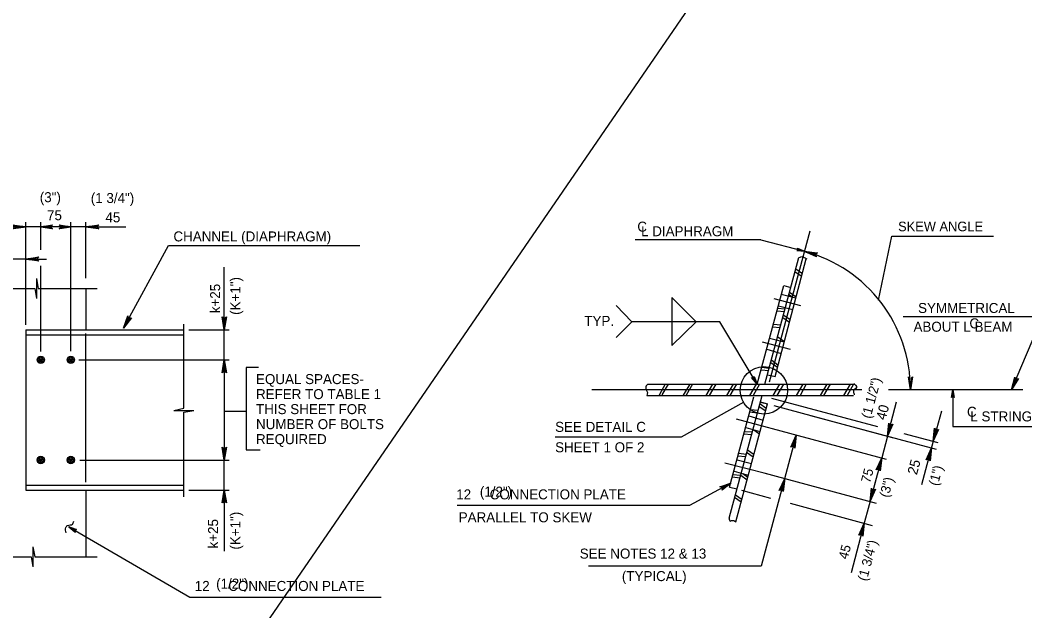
# Model space of a CAD drawing. Extents: x 634656 to 641360, y 298715 to 301183.
# Drawn here: x 640308.6 to 640609.6, y 299068.9 to 299246 of the extents above; entities that cross this region are included whole.
import ezdxf

# ---------------------------------------------------------------- set-up
doc = ezdxf.new("R2010")
doc.units = 0
for name, color, linetype in [('1', 7, 'Continuous'), ('2', 7, 'Continuous'), ('40', 7, 'Continuous')]:
    doc.layers.add(name, color=color, linetype=linetype)

msp = doc.modelspace()

# ---------------------------------------------------------------- linework, layer by layer
at = {"layer": '1'}
msp.add_line((641102.54, 300114.62), (640153.96, 298732.63), dxfattribs=at)
for points in [[(640306.55, 299184.47), (640306.69, 299184.2), (640310.24, 299184.01), (640306.55, 299184.47), (640306.36, 299184.63), (640310.24, 299184.01), (640306.69, 299183.83), (640306.56, 299183.57), (640310.24, 299184.01), (640306.36, 299183.39), (640306.56, 299183.57)], [(640318.06, 299183.54), (640317.94, 299183.81), (640314.74, 299184.01), (640318.06, 299183.54), (640318.23, 299183.38), (640314.74, 299184.01), (640317.94, 299184.18), (640318.05, 299184.45), (640314.74, 299184.01), (640318.23, 299184.62), (640318.05, 299184.45)], [(640320.42, 299184.47), (640320.55, 299184.2), (640323.74, 299184.01), (640320.42, 299184.47), (640320.25, 299184.63), (640323.74, 299184.01), (640320.55, 299183.83), (640320.43, 299183.57), (640323.74, 299184.01), (640320.25, 299183.39), (640320.43, 299183.57)], [(640331.93, 299183.54), (640331.8, 299183.81), (640328.24, 299184.01), (640331.93, 299183.54), (640332.12, 299183.38), (640328.24, 299184.01), (640331.79, 299184.18), (640331.92, 299184.45), (640328.24, 299184.01), (640332.12, 299184.62), (640331.92, 299184.45)], [(640313.93, 299173.92), (640313.8, 299174.19), (640310.24, 299174.38), (640313.93, 299173.92), (640314.12, 299173.76), (640310.24, 299174.38), (640313.79, 299174.56), (640313.92, 299174.82), (640310.24, 299174.38), (640314.12, 299175), (640313.92, 299174.82)], [(640547.03, 299175.27), (640546.97, 299175.56), (640543.59, 299176.67), (640547.03, 299175.27), (640547.17, 299175.06), (640543.59, 299176.67), (640547.06, 299175.92), (640547.25, 299176.14), (640543.59, 299176.67), (640547.49, 299176.26), (640547.25, 299176.14)], [(640341.66, 299156.65), (640341.36, 299156.66), (640339.49, 299153.63), (640341.66, 299156.65), (640341.9, 299156.74), (640339.49, 299153.63), (640341.04, 299156.83), (640340.87, 299157.08), (640339.49, 299153.63), (640340.81, 299157.34), (640340.87, 299157.08)], [(640370.21, 299156.82), (640369.94, 299156.69), (640369.74, 299153.13), (640370.21, 299156.82), (640370.37, 299157.01), (640369.74, 299153.13), (640369.57, 299156.68), (640369.3, 299156.81), (640369.74, 299153.13), (640369.13, 299157.01), (640369.3, 299156.81)], [(640369.28, 299140.44), (640369.55, 299140.58), (640369.74, 299144.13), (640369.28, 299140.44), (640369.12, 299140.25), (640369.74, 299144.13), (640369.92, 299140.58), (640370.18, 299140.45), (640369.74, 299144.13), (640370.36, 299140.25), (640370.18, 299140.45)], [(640575.77, 299138.84), (640575.5, 299138.7), (640575.29, 299135.15), (640575.77, 299138.84), (640575.94, 299139.03), (640575.29, 299135.15), (640575.13, 299138.7), (640574.87, 299138.83), (640575.29, 299135.15), (640574.69, 299139.03), (640574.87, 299138.83)], [(640607.48, 299138.42), (640607.18, 299138.4), (640605.61, 299135.2), (640607.48, 299138.42), (640607.7, 299138.53), (640605.61, 299135.2), (640606.83, 299138.54), (640606.64, 299138.76), (640605.61, 299135.2), (640606.56, 299139.01), (640606.64, 299138.76)], [(640569.85, 299124.73), (640569.55, 299124.67), (640568.45, 299121.28), (640569.85, 299124.73), (640570.05, 299124.87), (640568.45, 299121.28), (640569.19, 299124.76), (640568.97, 299124.95), (640568.45, 299121.28), (640568.85, 299125.19), (640568.97, 299124.95)], [(640539.72, 299118.16), (640540.01, 299118.23), (640541.12, 299121.61), (640539.72, 299118.16), (640539.52, 299118.02), (640541.12, 299121.61), (640540.37, 299118.13), (640540.6, 299117.94), (640541.12, 299121.61), (640540.71, 299117.7), (640540.6, 299117.94)], [(640583.56, 299123.17), (640583.27, 299123.11), (640582.15, 299119.73), (640583.56, 299123.17), (640583.77, 299123.31), (640582.15, 299119.73), (640582.91, 299123.2), (640582.69, 299123.39), (640582.15, 299119.73), (640582.57, 299123.63), (640582.69, 299123.39)], [(640370.21, 299117.82), (640369.94, 299117.69), (640369.74, 299114.13), (640370.21, 299117.82), (640370.37, 299118.01), (640369.74, 299114.13), (640369.57, 299117.68), (640369.3, 299117.81), (640369.74, 299114.13), (640369.13, 299118.01), (640369.3, 299117.81)], [(640580.2, 299114.3), (640580.49, 299114.36), (640581.61, 299117.74), (640580.2, 299114.3), (640579.99, 299114.16), (640581.61, 299117.74), (640580.85, 299114.27), (640581.07, 299114.08), (640581.61, 299117.74), (640581.19, 299113.84), (640581.07, 299114.08)], [(640565.3, 299111.34), (640565.59, 299111.4), (640566.71, 299114.78), (640565.3, 299111.34), (640565.09, 299111.2), (640566.71, 299114.78), (640565.95, 299111.31), (640566.18, 299111.12), (640566.71, 299114.78), (640566.29, 299110.88), (640566.18, 299111.12)], [(640536.24, 299105.14), (640536.53, 299105.21), (640537.64, 299108.59), (640536.24, 299105.14), (640536.03, 299105), (640537.64, 299108.59), (640536.89, 299105.11), (640537.11, 299104.92), (640537.64, 299108.59), (640537.23, 299104.68), (640537.11, 299104.92)], [(640564.63, 299105.23), (640564.33, 299105.17), (640563.21, 299101.79), (640564.63, 299105.23), (640564.83, 299105.37), (640563.21, 299101.79), (640563.97, 299105.26), (640563.75, 299105.46), (640563.21, 299101.79), (640563.63, 299105.7), (640563.75, 299105.46)], [(640369.28, 299101.44), (640369.55, 299101.58), (640369.74, 299105.13), (640369.28, 299101.44), (640369.12, 299101.25), (640369.74, 299105.13), (640369.92, 299101.58), (640370.18, 299101.45), (640369.74, 299105.13), (640370.36, 299101.25), (640370.18, 299101.45)], [(640560.06, 299091.72), (640560.35, 299091.78), (640561.46, 299095.17), (640560.06, 299091.72), (640559.86, 299091.58), (640561.46, 299095.17), (640560.71, 299091.69), (640560.94, 299091.5), (640561.46, 299095.17), (640561.06, 299091.26), (640560.94, 299091.5)]]:
    msp.add_lwpolyline(points, dxfattribs=at)
at = {"layer": '2'}
for p, q in [((640310.24, 299184.01), (640297.12, 299184.01)), ((640310.24, 299154.63), (640310.24, 299185.38)), ((640328.24, 299184.01), (640310.24, 299184.01)), ((640314.74, 299177.13), (640314.74, 299185.38)), ((640323.74, 299184.01), (640315.12, 299184.01)), ((640323.74, 299146.76), (640323.74, 299185.38)), ((640328.24, 299168.62), (640328.24, 299185.38)), ((640328.24, 299184.01), (640340.24, 299184.01)), ((640533.11, 299137.58), (640545.24, 299182.83)), ((640565.74, 299162.08), (640569.74, 299181.2)), ((640569.74, 299181.2), (640600.24, 299181.2)), ((640339.49, 299153.63), (640352.97, 299178.4)), ((640352.97, 299178.4), (640410.38, 299178.4)), ((640530.49, 299180.08), (640492.86, 299180.08)), ((640530.49, 299180.08), (640543.61, 299176.7)), ((640310.24, 299154.63), (640310.24, 299175.76)), ((640310.24, 299174.38), (640278.87, 299174.38)), ((640310.24, 299174.38), (640316.49, 299174.38)), ((640314.74, 299146.63), (640314.74, 299172.38)), ((640369.74, 299153.13), (640369.74, 299171.89)), ((640531.74, 299136.83), (640541.86, 299174.83)), ((640534.74, 299139.2), (640544.11, 299174.45)), ((640540.74, 299170.58), (640542.74, 299169.2)), ((640540.99, 299171.45), (640542.99, 299170.08)), ((640313.49, 299168.51), (640313.49, 299162.51)), ((640313.49, 299168.51), (640313.99, 299165.51)), ((640529.36, 299136.83), (640537.36, 299166.45)), ((640537.36, 299166.45), (640539.49, 299165.83)), ((640294.99, 299165.51), (640311.49, 299165.51)), ((640311.24, 299165.51), (640311.24, 299165.51)), ((640311.24, 299165.51), (640312.99, 299165.51)), ((640312.99, 299165.51), (640313.49, 299162.51)), ((640313.49, 299165.51), (640313.49, 299165.51)), ((640313.99, 299165.51), (640315.87, 299165.51)), ((640315.87, 299165.51), (640331.62, 299165.51)), ((640328.24, 299165.38), (640328.24, 299153.13)), ((640503.86, 299162.83), (640503.86, 299155.58)), ((640503.86, 299162.83), (640511.11, 299155.58)), ((640536.61, 299163.83), (640540.99, 299162.7)), ((640538.99, 299163.7), (640540.11, 299162.83)), ((640539.11, 299164.45), (640541.11, 299163.08)), ((640534.36, 299162.58), (640542.36, 299160.45)), ((640535.74, 299160.33), (640540.11, 299159.2)), ((640537.61, 299158.58), (640535.24, 299158.7)), ((640537.74, 299159.33), (640535.49, 299159.58)), ((640537.11, 299156.83), (640539.11, 299155.45)), ((640537.36, 299157.58), (640539.24, 299156.2)), ((640614.86, 299157.08), (640573.11, 299157.08)), ((640605.61, 299135.2), (640614.86, 299157.08)), ((640357.62, 299131.38), (640357.62, 299154.88)), ((640518.24, 299155.58), (640491.86, 299155.58)), ((640503.86, 299155.58), (640503.86, 299148.45)), ((640503.86, 299148.45), (640511.11, 299155.58)), ((640529.36, 299136.83), (640518.24, 299155.58)), ((640536.24, 299153.7), (640533.99, 299153.95)), ((640536.49, 299154.58), (640534.24, 299154.7)), ((640310.24, 299153.13), (640357.62, 299153.13)), ((640310.24, 299153.13), (640310.24, 299105.13)), ((640310.24, 299151.63), (640357.62, 299151.63)), ((640328.24, 299107.51), (640328.24, 299152.01)), ((640359.12, 299153.13), (640371.24, 299153.13)), ((640369.74, 299144.13), (640369.74, 299153.13)), ((640535.61, 299151.08), (640537.61, 299149.7)), ((640530.86, 299149.58), (640539.24, 299147.33)), ((640533.11, 299150.7), (640537.49, 299149.58)), ((640532.24, 299147.33), (640536.61, 299146.08)), ((640314.74, 299144.13), (640314.74, 299144.13)), ((640323.74, 299144.13), (640323.74, 299144.13)), ((640326.12, 299144.13), (640371.24, 299144.13)), ((640369.74, 299144.13), (640369.74, 299114.13)), ((640376.24, 299141.88), (640376.24, 299117.13)), ((640379.99, 299141.88), (640376.24, 299141.88)), ((640532.99, 299141.58), (640530.74, 299141.83)), ((640533.49, 299143.33), (640535.49, 299141.95)), ((640533.74, 299144.08), (640535.61, 299142.7)), ((640532.86, 299140.83), (640530.61, 299141.08)), ((640532.61, 299139.7), (640534.74, 299139.2)), ((640496.61, 299136.83), (640558.61, 299136.83)), ((640501.86, 299136.83), (640499.99, 299133.58)), ((640502.74, 299136.83), (640500.86, 299133.7)), ((640509.24, 299136.83), (640507.24, 299133.58)), ((640509.99, 299136.83), (640508.11, 299133.58)), ((640515.99, 299136.83), (640513.99, 299133.45)), ((640516.99, 299136.83), (640514.99, 299133.45)), ((640522.24, 299136.83), (640520.24, 299133.45)), ((640523.24, 299136.83), (640521.24, 299133.45)), ((640529.11, 299136.83), (640527.11, 299133.45)), ((640530.11, 299136.83), (640528.24, 299133.45)), ((640536.11, 299136.83), (640534.11, 299133.45)), ((640537.24, 299136.83), (640535.24, 299133.45)), ((640543.11, 299136.83), (640541.11, 299133.45)), ((640544.11, 299136.83), (640542.24, 299133.45)), ((640550.24, 299136.83), (640548.24, 299133.45)), ((640551.24, 299136.83), (640549.24, 299133.45)), ((640557.24, 299136.83), (640555.24, 299133.45)), ((640558.24, 299136.83), (640556.36, 299133.45)), ((640560.72, 299135.2), (640479.86, 299135.2)), ((640496.36, 299133.45), (640558.24, 299133.45)), ((640511.86, 299135.2), (640511.86, 299135.2)), ((640520.99, 299096.7), (640530.86, 299133.45)), ((640521.11, 299105.95), (640528.36, 299133.08)), ((640533.67, 299132.7), (640565.46, 299124.18)), ((640608.99, 299135.2), (640568.73, 299135.2)), ((640588.01, 299135.2), (640588.01, 299124.2)), ((640357.62, 299129.63), (640357.62, 299131.38)), ((640525.36, 299131.45), (640506.61, 299120.95)), ((640522.99, 299095.58), (640532.49, 299130.95)), ((640529.99, 299130.2), (640531.99, 299128.83)), ((640530.24, 299131.08), (640532.11, 299129.7)), ((640530.36, 299131.58), (640532.49, 299130.95)), ((640530.36, 299131.45), (640532.49, 299130.95)), ((640534.38, 299130.45), (640569.83, 299120.92)), ((640568.45, 299121.28), (640571.17, 299131.55)), ((640354.62, 299129.01), (640357.62, 299129.63)), ((640354.62, 299129.01), (640360.62, 299129.01)), ((640357.62, 299128.51), (640360.62, 299129.01)), ((640357.62, 299129.01), (640357.62, 299129.01)), ((640357.62, 299126.76), (640357.62, 299128.51)), ((640357.62, 299127.76), (640357.62, 299127.76)), ((640357.62, 299103.13), (640357.62, 299127.01)), ((640369.74, 299128.76), (640376.37, 299128.76)), ((640526.86, 299127.33), (640531.24, 299126.08)), ((640529.49, 299128.2), (640527.11, 299128.45)), ((640529.61, 299128.95), (640527.36, 299129.2)), ((640545.36, 299127.5), (640582.99, 299117.37)), ((640584.61, 299128.81), (640582.15, 299119.73)), ((640523.11, 299126.45), (640536.47, 299122.84)), ((640525.99, 299123.83), (640530.24, 299122.7)), ((640588.01, 299124.2), (640624.76, 299124.2)), ((640506.61, 299120.95), (640468.86, 299120.95)), ((640527.74, 299121.7), (640525.36, 299121.83)), ((640527.86, 299122.45), (640525.61, 299122.58)), ((640528.11, 299123.33), (640530.11, 299121.95)), ((640541.12, 299121.61), (640530.61, 299082.33)), ((640536.47, 299122.85), (640568.08, 299114.42)), ((640568.45, 299121.28), (640566.71, 299114.79)), ((640573.33, 299122.08), (640583.49, 299119.37)), ((640582.15, 299119.73), (640578.61, 299106.67)), ((640376.24, 299117.13), (640380.49, 299117.13)), ((640525.86, 299115.08), (640523.61, 299115.33)), ((640526.11, 299115.83), (640523.86, 299116.08)), ((640526.24, 299116.45), (640528.24, 299115.08)), ((640526.49, 299117.2), (640528.49, 299115.83)), ((640566.71, 299114.78), (640564.46, 299106.42)), ((640314.74, 299114.13), (640314.74, 299114.13)), ((640323.74, 299114.13), (640323.74, 299114.13)), ((640326.49, 299114.13), (640371.24, 299114.13)), ((640369.74, 299105.13), (640369.74, 299114.13)), ((640519.74, 299113.33), (640532.27, 299110.06)), ((640523.36, 299114.2), (640527.74, 299113.08)), ((640524.24, 299108.7), (640521.99, 299108.95)), ((640524.36, 299109.45), (640522.11, 299109.7)), ((640522.49, 299110.83), (640526.74, 299109.58)), ((640524.49, 299109.58), (640526.36, 299108.2)), ((640525.11, 299110.08), (640526.61, 299108.95)), ((640531.44, 299110.26), (640565.08, 299101.17)), ((640565.46, 299110.04), (640563.21, 299101.79)), ((640310.24, 299106.63), (640357.62, 299106.63)), ((640521.49, 299107.2), (640509.11, 299100.45)), ((640521.11, 299105.95), (640523.36, 299105.45)), ((640310.24, 299105.13), (640357.62, 299105.13)), ((640328.24, 299105.13), (640328.24, 299085.13)), ((640359.12, 299105.13), (640371.24, 299105.13)), ((640369.74, 299105.13), (640369.74, 299086.76)), ((640522.61, 299102.95), (640524.61, 299101.58)), ((640522.86, 299103.7), (640524.86, 299102.33)), ((640524.74, 299105.08), (640533.36, 299102.7)), ((640509.11, 299100.45), (640439.46, 299100.45)), ((640539.32, 299101.15), (640563.83, 299094.54)), ((640563.21, 299101.79), (640560.96, 299093.42)), ((640323.12, 299094.13), (640359.36, 299073)), ((640561.46, 299095.17), (640557.52, 299080.35)), ((640312.37, 299088.13), (640312.37, 299082.13)), ((640312.37, 299088.13), (640312.99, 299085.13)), ((640295.87, 299085.13), (640310.12, 299085.13)), ((640310.12, 299085.13), (640311.87, 299085.13)), ((640311.87, 299085.13), (640312.37, 299082.13)), ((640312.37, 299085.13), (640312.37, 299085.13)), ((640312.99, 299085.13), (640314.74, 299085.13)), ((640313.49, 299085.13), (640313.49, 299085.13)), ((640314.24, 299085.13), (640331.62, 299085.13)), ((640530.61, 299082.33), (640478.86, 299082.33)), ((640359.36, 299073), (640416.75, 299073))]:
    msp.add_line(p, q, dxfattribs=at)
for points in [[(640541.49, 299177.45), (640541.61, 299177.33), (640543.61, 299176.7), (640541.49, 299177.45), (640541.49, 299177.58), (640543.61, 299176.7), (640541.49, 299177.08), (640541.36, 299176.95), (640543.61, 299176.7), (640541.24, 299176.95), (640541.36, 299176.95)], [(640487.11, 299160.45), (640491.86, 299155.58), (640487.11, 299150.83)], [(640528.36, 299139.08), (640528.36, 299138.83), (640529.36, 299136.83), (640528.36, 299139.08), (640528.49, 299139.2), (640529.36, 299136.83), (640528.11, 299138.7), (640527.86, 299138.7), (640529.36, 299136.83), (640527.74, 299138.83), (640527.86, 299138.7)], [(640587.76, 299132.95), (640587.89, 299133.08), (640588.01, 299135.2), (640587.76, 299132.95), (640587.64, 299132.83), (640588.01, 299135.2), (640588.14, 299133.08), (640588.39, 299132.95), (640588.01, 299135.2), (640588.39, 299132.83), (640588.39, 299132.95)], [(640518.49, 299106.08), (640518.74, 299105.83), (640521.49, 299107.2), (640518.49, 299106.08), (640518.24, 299106.08), (640521.49, 299107.2), (640518.86, 299105.58), (640518.86, 299105.33), (640521.49, 299107.2), (640518.86, 299105.08), (640518.86, 299105.33)], [(640324.99, 299092.63), (640324.99, 299092.88), (640323.12, 299094.13), (640324.99, 299092.63), (640325.12, 299092.51), (640323.12, 299094.13), (640325.12, 299093.13), (640325.37, 299093.26), (640323.12, 299094.13), (640325.49, 299093.26), (640325.37, 299093.26)]]:
    msp.add_lwpolyline(points, dxfattribs=at)
for centre, radius in [((640314.74, 299144.14), 1.11), ((640314.74, 299144.14), 0.792), ((640323.74, 299144.14), 1.11), ((640323.74, 299144.14), 0.792), ((640314.74, 299144.14), 0.433), ((640314.74, 299144.14), 0.219), ((640314.74, 299144.14), 0.0937), ((640323.74, 299144.14), 0.433), ((640323.74, 299144.14), 0.219), ((640323.74, 299144.14), 0.0937), ((640531.41, 299135.01), 7.1), ((640314.74, 299114.14), 1.11), ((640314.74, 299114.14), 0.792), ((640323.74, 299114.14), 1.11), ((640323.74, 299114.14), 0.792), ((640314.74, 299114.14), 0.433), ((640314.74, 299114.14), 0.219), ((640314.74, 299114.14), 0.0937), ((640323.74, 299114.14), 0.433), ((640323.74, 299114.14), 0.219), ((640323.74, 299114.14), 0.0937)]:
    msp.add_circle(centre, radius, dxfattribs=at)
msp.add_arc((640532.54, 299135.37), 42.76, 359.7137, 75.0215, dxfattribs=at)
for points in [[(640541.99, 299174.83), (640542.49, 299175.08), (640543.11, 299175.08), (640543.49, 299174.83), (640543.99, 299174.58), (640544.24, 299174.45)], [(640496.61, 299136.83), (640496.11, 299136.33), (640496.11, 299135.2), (640496.49, 299134.33), (640496.36, 299133.45)], [(640558.36, 299137.08), (640559.11, 299136.2), (640558.99, 299135.58), (640558.36, 299135.2), (640558.24, 299134.58), (640558.49, 299133.7)], [(640520.99, 299096.7), (640521.36, 299095.83), (640521.74, 299095.95), (640522.36, 299095.95), (640522.99, 299095.58)], [(640322.37, 299092.26), (640322.24, 299093.88), (640322.74, 299094.51), (640324.24, 299094.88), (640324.62, 299095.76)]]:
    msp.add_spline(points, degree=3, dxfattribs=at)

# ---------------------------------------------------------------- texts
for s, height, p in [('75', 3, (640316.62, 299186.01)), ('45', 3, (640334.12, 299185.38)), ('C', 3, (640493.49, 299182.58)), ('L DIAPHRAGM', 3, (640494.61, 299181.2)), ('SKEW ANGLE', 2.879, (640571.61, 299182.7)), ('CHANNEL (DIAPHRAGM)', 3, (640354.5, 299179.65)), ('SYMMETRICAL', 3, (640577.61, 299158.2)), ('TYP.', 3, (640477.61, 299154.33)), ('ABOUT L BEAM', 3, (640576.24, 299152.58)), ('C', 3, (640592.99, 299153.58)), ('EQUAL SPACES-', 3, (640379.24, 299136.88)), ('REFER TO TABLE 1', 3, (640379.24, 299132.38)), ('THIS SHEET FOR', 3, (640379.24, 299127.88)), ('C', 3, (640592.26, 299127.08)), ('L STRINGER', 3, (640593.26, 299125.7)), ('NUMBER OF BOLTS', 3, (640379.24, 299123.38)), ('SEE DETAIL C', 3, (640468.86, 299122.57)), ('REQUIRED', 3, (640379.24, 299118.88)), ('SHEET 1 OF 2', 3, (640468.86, 299116.45)), ('12     CONNECTION PLATE', 3, (640439.23, 299102.33)), ('PARALLEL TO SKEW', 3, (640439.97, 299095.45)), ('SEE NOTES 12 & 13  ', 3, (640476.24, 299084.58)), ('(TYPICAL)', 3, (640488.86, 299077.83)), ('12     CONNECTION PLATE', 3, (640360.89, 299074.88))]:
    msp.add_text(s, height=height, dxfattribs=at).set_placement(p)
for s, height, rotation, p in [(' k+25 ', 3, 90, (640368.49, 299157.01)), ('40', 3, 75.0076, (640567.83, 299125.92)), ('25 ', 3, 74.9759, (640577.24, 299109.5)), ('75', 2.875, 75.0282, (640563.21, 299107.04)), (' k+25 ', 3, 90, (640367.87, 299086.51)), ('45', 2.875, 74.9886, (640556.46, 299084.17))]:
    msp.add_text(s, height=height, rotation=rotation, dxfattribs=at).set_placement(p)
at = {"layer": '40'}
for s, p in [('(3")', (640314.45, 299191.41)), ('(1 3/4")', (640329.73, 299191.16)), ('(1/2")', (640446.3, 299103.15)), ('(1/2")', (640367.29, 299075.58))]:
    msp.add_text(s, height=3, dxfattribs=at).set_placement(p)
for s, height, rotation, p in [('(K+1")', 3, 90, (640374.53, 299157.63)), ('(1 1/2")', 2.875, 74.9886, (640563.34, 299126.37)), ('(1")', 2.875, 74.9886, (640583.5, 299106.21)), ('(3")', 2.875, 74.9886, (640568.73, 299102.7)), ('(K+1")', 3, 90, (640374.53, 299087.27)), ('(1 3/4")', 2.875, 74.9886, (640562.22, 299077.66))]:
    msp.add_text(s, height=height, rotation=rotation, dxfattribs=at).set_placement(p)

doc.saveas('drawing.dxf')
